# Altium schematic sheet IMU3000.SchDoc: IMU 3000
size Letter
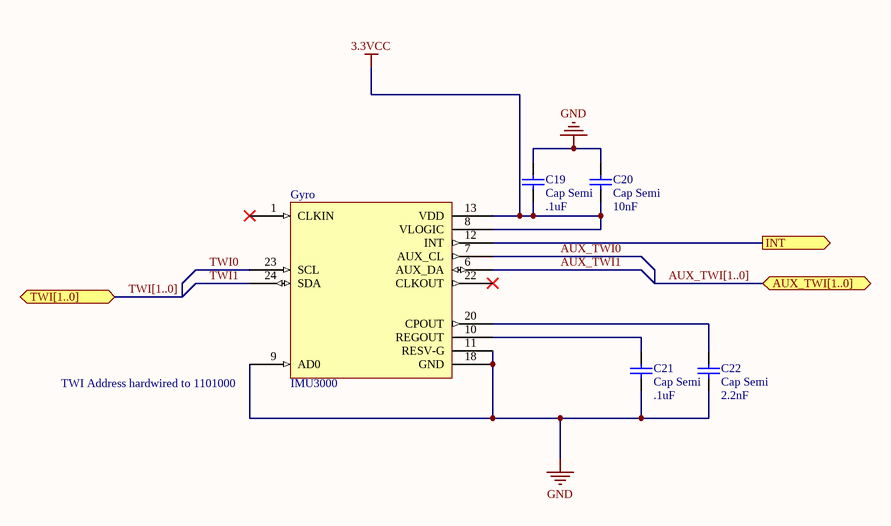
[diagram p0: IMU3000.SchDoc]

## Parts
C19  Cap Semi  value .1uF  [CAPC2012N]
C20  Cap Semi  value 10nF  [CAPC2012N]
C21  Cap Semi  value .1uF  [CAPC2012N]
C22  Cap Semi  value 2.2nF  [CAPC2012N]
Gyro  IMU3000  [IMU3000 - ECESHOP]

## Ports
AUX_TWI[1..0] (bidir), INT (out), TWI[1..0] (bidir)

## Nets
3.3VCC: C19.2 C20.2 Gyro.8(VLOGIC) Gyro.13(VDD)
GND: C19.1 C20.1 C21.1 C22.1 Gyro.9(AD0) Gyro.11(RESV-G) Gyro.18(GND)
AUX_TWI0: Gyro.7(AUX_CL)
AUX_TWI1: Gyro.6(AUX_DA)
INT: Gyro.12(INT) ; port INT
TWI0: Gyro.23(SCL)
TWI1: Gyro.24(SDA)
NetC21_2: C21.2 Gyro.10(REGOUT)
NetC22_2: C22.2 Gyro.20(CPOUT)

Not connected (* = marked no-connect by the designer): Gyro 1(CLKIN)* 22(CLKOUT)*

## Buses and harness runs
bus AUX_TWI[1..0] = port AUX_TWI[1..0]
bus TWI[1..0] = port TWI[1..0]

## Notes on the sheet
- (near Gyro) TWI Address hardwired to 1101000

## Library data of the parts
C19-C22 = Cap Semi: Capacitor (Semiconductor SIM Model)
